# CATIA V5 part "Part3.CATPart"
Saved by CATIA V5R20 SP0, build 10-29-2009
Part number: Part3
Bounding box of the stored display mesh (mm): x -10 to 10, y -10 to 10, z -12 to 12
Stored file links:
  E:\Ehsan\Amoozesh\CATIA\CATIA Course\Advanced\Exercises\DMU Kinematic\12\Part3.CATPart
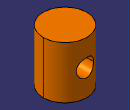
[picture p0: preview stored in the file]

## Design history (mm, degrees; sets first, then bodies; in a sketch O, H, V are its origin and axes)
Body1 (main body)
  Sketch1 on xy-plane, origin (0, 0, 0), H (1, 0, 0), V (0, 1, 0)
    circle A1 centre (0, 0) radius 10
    radius A1 = 10
  Pad1: profile Sketch1, direction (0, 0, 1), length 12, mirrored extent
  Sketch2 on zx-plane, origin (0, 0, 0), H (-1, 0, 0), V (0, 0, 1)
    circle A1 centre (0, 0) radius 4
    radius A1 = 4
  Pocket1: profile Sketch2, direction (0, -1, 0), length 12, mirrored extent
